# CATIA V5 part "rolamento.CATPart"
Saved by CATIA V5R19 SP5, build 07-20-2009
Part number: rolamento
Bounding box of the stored display mesh (mm): x 0 to 8, y -13 to 13, z -12.803 to 12.803
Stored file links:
  Z:\UA\ATLAS\atlascar\ServoPiloto\dir\suportePotenciometro\potenciometro\rolamento.CATPart
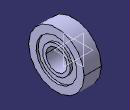
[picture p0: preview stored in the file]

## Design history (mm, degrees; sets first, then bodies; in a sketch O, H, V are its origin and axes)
Body1 (main body)
  Sketch1 on yz-plane, origin (0, 0, 0), H (0, 1, 0), V (0, 0, 1)
    circle A1 centre (0, 0) radius 5
    circle A2 centre (0, 0) radius 13
    radius A1 = 5
    radius A2 = 13
  Pad1: profile Sketch1, direction (1, 0, 0), length 8
  Sketch2 on zx-plane, origin (0, 0, 0), H (-1, 0, 0), V (0, 0, 1)
    line L1 (-1, 9.5424) -> (1.1929, 9.5424)
    line L2 (1.1929, 9.5424) -> (1.1929, 6.5)
    line L3 (1.1929, 6.5) -> (-1, 6.5)
    line L4 (-1, 6.5) -> (-1, 9.5424)
    point P5 (-10.8519, 9.5424)
    line L5 (-10.8519, 9.5424) -> (-7, 9.5424)
    line L6 (-7, 9.5424) -> (-7, 6.5)
    line L7 (-7, 6.5) -> (-10.8519, 6.5)
    line L8 (-10.8519, 6.5) -> (-10.8519, 9.5424)
    point P7 (-7, 6.5)
    distance L6 L4 = 6
    distance V L4 = 1
    distance L3 H = 6.5
    horizontal: L1 H, L3 H, L5 H, L7 H
    vertical: L2 V, L4 V, L6 V, L8 V
    coincidence: P5 L1, P7 L3
  Groove1: profile Sketch2, axis axis of face of Pad1 from Sketch1.A1, angle 360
